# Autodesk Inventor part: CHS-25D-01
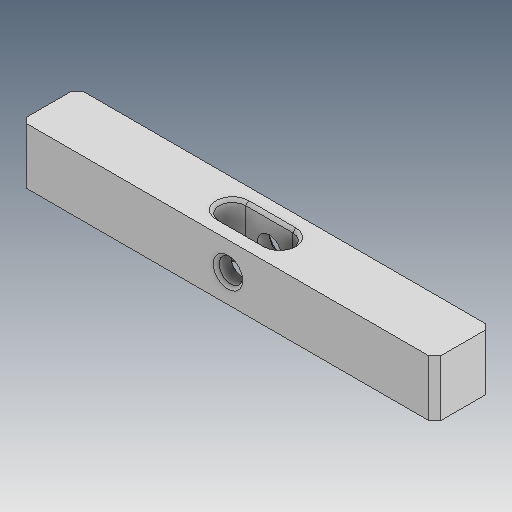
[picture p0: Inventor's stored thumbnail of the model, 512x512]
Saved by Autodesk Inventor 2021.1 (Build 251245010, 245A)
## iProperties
Created: 2019-04
Part Number: CHS-25D-01
Material: Ogólny
Document SubType Name: Modeling
Designer: user
Density: 1 g/cm^3
Appearance: Domyślna
Author: user
Revision Number: ÈÎºÎ
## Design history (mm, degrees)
feature "ÊäÈë1"
node "Bryła1"
